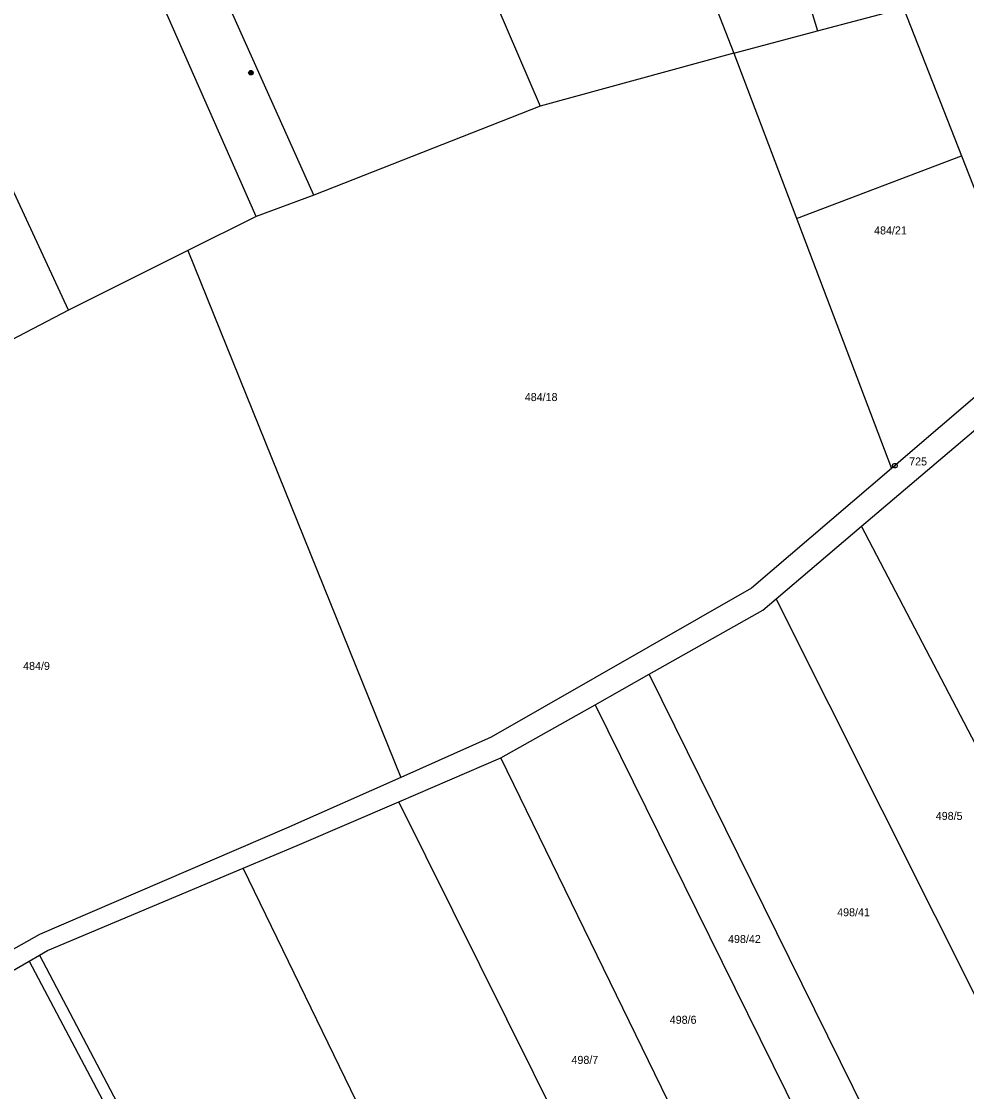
# Model space of a CAD drawing. Extents: x -694465 to -690527, y -983694 to -978978.
# Drawn here: x -693834.3 to -693633.5, y -981788.7 to -981561.4 of the extents above; entities that cross this region are included whole.
import ezdxf

# ---------------------------------------------------------------- set-up
doc = ezdxf.new("R2010")
doc.units = 0
for name, color, linetype in [('Vrstva 1', 7, 'Continuous'), ('Vrstva 18', 7, 'Continuous'), ('Vrstva 24', 7, 'Continuous'), ('Vrstva 26', 7, 'Continuous'), ('Vrstva 60', 7, 'Continuous')]:
    doc.layers.add(name, color=color, linetype=linetype)

msp = doc.modelspace()

# ---------------------------------------------------------------- linework, layer by layer
at = {"layer": 'Vrstva 1'}
msp.add_line((-693682.95, -981568.17), (-693649.412, -981656.344), dxfattribs=at)
for points in [[(-693784.41, -981602.81), (-693830.69, -981497.86)], [(-693772.17, -981598.3), (-693815.02, -981502.79)], [(-693824.25, -981622.71), (-693877.43, -981508.24)], [(-693681.999, -981508.221), (-693665.12, -981563.444)], [(-693754.09, -981509.6), (-693724.1, -981579.44)], [(-693705.4, -981510.72), (-693682.95, -981568.17)], [(-693665.12, -981563.444), (-693646.88, -981558.61)], [(-693646.88, -981558.61), (-693625.23, -981613.78)], [(-693682.95, -981568.17), (-693665.12, -981563.444)], [(-693682.95, -981568.17), (-693724.1, -981579.44)], [(-693724.1, -981579.44), (-693772.17, -981598.3)], [(-693772.17, -981598.3), (-693784.41, -981602.81)], [(-693784.41, -981602.81), (-693798.94, -981610.07)], [(-693798.94, -981610.07), (-693824.25, -981622.71)], [(-693798.94, -981610.07), (-693753.68, -981721.96)], [(-693824.25, -981622.71), (-693916.12, -981670.72)], [(-693618.89, -981630.26), (-693649.412, -981656.344)], [(-693655.78, -981668.61), (-693614.21, -981633.33)], [(-693649.412, -981656.344), (-693679.2, -981681.8)], [(-693673.94, -981684.03), (-693655.78, -981668.61)], [(-693605.65, -981764.46), (-693655.78, -981668.61)], [(-693679.2, -981681.8), (-693734.45, -981713.44)], [(-693676.75, -981686.41), (-693673.94, -981684.03)], [(-693617.65, -981796.24), (-693673.94, -981684.03)], [(-693700.9, -981700.04), (-693676.75, -981686.41)], [(-693712.38, -981706.52), (-693700.9, -981700.04)], [(-693649.44, -981804.32), (-693700.9, -981700.04)], [(-693732.4, -981717.82), (-693712.38, -981706.52)], [(-693712.38, -981706.52), (-693663.83, -981804.9)], [(-693734.45, -981713.44), (-693753.68, -981721.96)], [(-693754.08, -981727.11), (-693732.4, -981717.82)], [(-693676.48, -981832.51), (-693732.4, -981717.82)], [(-693753.68, -981721.96), (-693777.99, -981732.73)], [(-693775.71, -981736.38), (-693754.08, -981727.11)], [(-693696.65, -981842.65), (-693754.08, -981727.11)], [(-693777.99, -981732.73), (-693830.46, -981755.31)], [(-693787.14, -981741.2), (-693775.71, -981736.38)], [(-693828.75, -981758.73), (-693787.14, -981741.2)], [(-693730.54, -981857.82), (-693787.14, -981741.2)], [(-693830.46, -981755.31), (-693872.4, -981778.87)], [(-693830.46, -981759.72), (-693828.75, -981758.73)], [(-693878.47, -981787.48), (-693832.64, -981760.98)], [(-693832.64, -981760.98), (-693830.46, -981759.72)], [(-693832.64, -981760.98), (-693771.68, -981876.23)], [(-693830.46, -981759.72), (-693769.59, -981875.31)]]:
    msp.add_lwpolyline(points, dxfattribs=at)
at = {"layer": 'Vrstva 24'}
msp.add_lwpolyline([(-693648.566, -981655.284), (-693648.316, -981655.466), (-693648.22, -981655.76), (-693648.316, -981656.054), (-693648.566, -981656.236), (-693648.874, -981656.236), (-693649.124, -981656.054), (-693649.22, -981655.76), (-693649.124, -981655.466), (-693648.874, -981655.284)], close=True, dxfattribs=at)
msp.add_lwpolyline([(-693648.839, -981655.76), (-693648.6, -981655.76)], dxfattribs=at)
at = {"layer": 'Vrstva 26'}
msp.add_lwpolyline([(-693785.675, -981571.844), (-693785.365, -981571.844), (-693785.115, -981572.026), (-693785.02, -981572.32), (-693785.115, -981572.614), (-693785.365, -981572.796), (-693785.675, -981572.796), (-693785.925, -981572.614), (-693786.02, -981572.32), (-693785.925, -981572.026), (-693785.675, -981571.844), (-693785.64, -981571.88), (-693785.4, -981571.88), (-693785.24, -981571.96), (-693785.8, -981571.96), (-693785.88, -981572.04), (-693785.16, -981572.04), (-693785.16, -981572.12), (-693785.88, -981572.12), (-693785.922, -981572.2), (-693785.12, -981572.201), (-693785.08, -981572.28), (-693785.96, -981572.28), (-693785.96, -981572.36), (-693785.08, -981572.36), (-693785.111, -981572.439), (-693785.925, -981572.439), (-693785.919, -981572.52), (-693785.111, -981572.52), (-693785.16, -981572.6), (-693785.88, -981572.6), (-693785.8, -981572.68), (-693785.24, -981572.68), (-693785.348, -981572.759), (-693785.688, -981572.759)], dxfattribs=at)
msp.add_lwpolyline([(-693785.675, -981571.844), (-693785.365, -981571.844), (-693785.115, -981572.026), (-693785.02, -981572.32), (-693785.115, -981572.614), (-693785.365, -981572.796), (-693785.675, -981572.796), (-693785.925, -981572.614), (-693786.02, -981572.32), (-693785.925, -981572.026), (-693785.675, -981571.844), (-693785.64, -981571.88), (-693785.4, -981571.88), (-693785.24, -981571.96), (-693785.8, -981571.96), (-693785.88, -981572.04), (-693785.16, -981572.04), (-693785.16, -981572.12), (-693785.88, -981572.12), (-693785.922, -981572.2), (-693785.12, -981572.201), (-693785.08, -981572.28), (-693785.96, -981572.28), (-693785.96, -981572.36), (-693785.08, -981572.36), (-693785.111, -981572.439), (-693785.925, -981572.439), (-693785.919, -981572.52), (-693785.111, -981572.52), (-693785.16, -981572.6), (-693785.88, -981572.6), (-693785.8, -981572.68), (-693785.24, -981572.68), (-693785.348, -981572.759), (-693785.688, -981572.759)], dxfattribs=at)
msp.add_lwpolyline([(-693785.675, -981571.844), (-693785.365, -981571.844), (-693785.115, -981572.026), (-693785.02, -981572.32), (-693785.115, -981572.614), (-693785.365, -981572.796), (-693785.675, -981572.796), (-693785.925, -981572.614), (-693786.02, -981572.32), (-693785.925, -981572.026), (-693785.675, -981571.844), (-693785.64, -981571.88), (-693785.4, -981571.88), (-693785.24, -981571.96), (-693785.8, -981571.96), (-693785.88, -981572.04), (-693785.16, -981572.04), (-693785.16, -981572.12), (-693785.88, -981572.12), (-693785.922, -981572.2), (-693785.12, -981572.201), (-693785.08, -981572.28), (-693785.96, -981572.28), (-693785.96, -981572.36), (-693785.08, -981572.36), (-693785.111, -981572.439), (-693785.925, -981572.439), (-693785.919, -981572.52), (-693785.111, -981572.52), (-693785.16, -981572.6), (-693785.88, -981572.6), (-693785.8, -981572.68), (-693785.24, -981572.68), (-693785.348, -981572.759), (-693785.688, -981572.759)], dxfattribs=at)
at = {"layer": 'Vrstva 60'}
msp.add_line((-693669.599, -981603.271), (-693634.581, -981589.951), dxfattribs=at)

# ---------------------------------------------------------------- texts
at = {"layer": 'Vrstva 18'}
for s, p in [('484/21', (-693653.115, -981606.65)), ('484/18', (-693727.333, -981642.04)), ('725', (-693645.665, -981655.71)), ('484/9', (-693833.923, -981699.13)), ('498/5', (-693640.013, -981730.98)), ('498/41', (-693660.963, -981751.44)), ('498/42', (-693684.143, -981757.12)), ('498/6', (-693696.533, -981774.27)), ('498/7', (-693717.413, -981782.78))]:
    msp.add_text(s, height=1.7, dxfattribs=at).set_placement(p)

doc.saveas('drawing.dxf')
